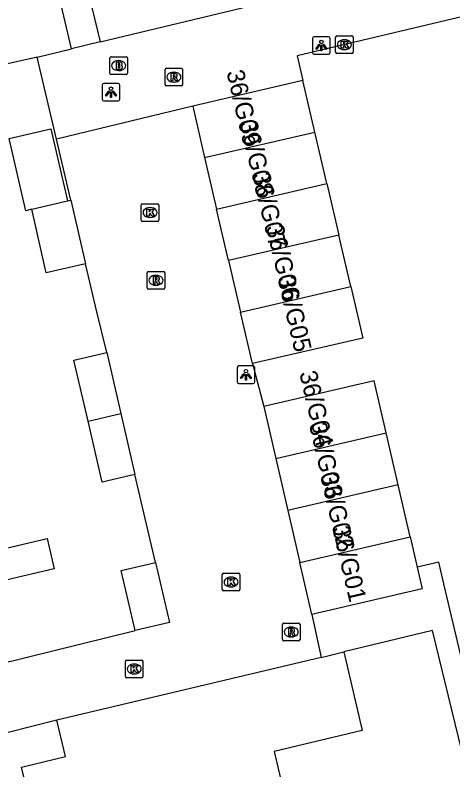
# Model space of a CAD drawing. Extents: x 158038 to 159242, y 380133 to 381214.
# Drawn here: x 158792.72 to 158817.61, y 380691.2 to 380734.09 of the extents above; entities that cross this region are included whole.
import ezdxf

# ---------------------------------------------------------------- set-up
doc = ezdxf.new("R2010")
doc.units = 0
for name, color, linetype in [('IMGEO_Brandkraan', 7, 'Continuous'), ('IMGEO_Kolk', 7, 'Continuous'), ('IMGEO_Lichtpunt', 7, 'Continuous'), ('IMGEO_Muur', 7, 'Continuous'), ('IMGEO_Pand', 7, 'Continuous'), ('IMGEO_Pand_nummerreeks', 7, 'Continuous'), ('IMGEO_Rijbaan_lokaal_open', 7, 'Continuous'), ('IMGEO_Rioolput', 7, 'Continuous'), ('IMGEO_Voetpad_open', 7, 'Continuous')]:
    doc.layers.add(name, color=color, linetype=linetype)

msp = doc.modelspace()

# ---------------------------------------------------------------- linework, layer by layer
at = {"layer": 'IMGEO_Brandkraan'}
for p, q in [((158798.109, 380730.793), (158798.109, 380731.645)), ((158798.184, 380731.719), (158799.036, 380731.719)), ((158799.11, 380731.645), (158799.11, 380730.793)), ((158798.597, 380731.499), (158798.622, 380731.499)), ((158799.036, 380730.719), (158798.184, 380730.719)), ((158798.62, 380730.939), (158798.595, 380730.939))]:
    msp.add_line(p, q, dxfattribs=at)
for points in [[(158798.109, 380730.793), (158798.109, 380731.645)], [(158798.184, 380731.719), (158799.036, 380731.719)], [(158799.11, 380731.645), (158799.11, 380730.793)], [(158798.457, 380731.419), (158798.457, 380731.019), (158798.67, 380731.019)], [(158798.688, 380731.419), (158798.457, 380731.419)], [(158798.636, 380731.338), (158798.582, 380731.338), (158798.582, 380731.262)], [(158798.582, 380731.262), (158798.635, 380731.262)], [(158798.644, 380731.186), (158798.582, 380731.186), (158798.582, 380731.105)], [(158799.036, 380730.719), (158798.184, 380730.719)], [(158798.582, 380731.105), (158798.644, 380731.105)]]:
    msp.add_lwpolyline(points, dxfattribs=at)
for centre, radius, start, end in [((158798.186, 380731.643), 0.0765, 91.552, 178.448), ((158798.186, 380731.643), 0.0765, 91.552, 178.448), ((158799.034, 380731.643), 0.0765, 1.552, 88.448), ((158799.034, 380731.643), 0.0765, 1.552, 88.448), ((158798.637, 380731.3), 0.0379, 267.8285, 90.9355), ((158798.645, 380731.145), 0.0404, 269.8759, 90.5077), ((158798.692, 380731.274), 0.145, 59.4692, 91.5367), ((158798.717, 380731.321), 0.0922, 285.5137, 58.1501), ((158798.722, 380731.129), 0.105, 301.3115, 78.989), ((158798.186, 380730.795), 0.0765, 181.552, 268.448), ((158798.186, 380730.795), 0.0765, 181.552, 268.448), ((158798.676, 380731.27), 0.251, 268.6676, 293.5347), ((158799.034, 380730.795), 0.0765, 271.552, 358.448), ((158799.034, 380730.795), 0.0765, 271.552, 358.448)]:
    msp.add_arc(centre, radius, start, end, dxfattribs=at)
for centre, major_axis, ratio, start_param, end_param in [((158798.596, 380731.219), (-0.387, 0.002), 0.722429, 4.712389, 7.853982), ((158798.621, 380731.219), (-0.39, 0.002), 0.717154, 1.570796, 4.712389)]:
    msp.add_ellipse(centre, major_axis=major_axis, ratio=ratio, start_param=start_param, end_param=end_param, dxfattribs=at)
at = {"layer": 'IMGEO_Kolk'}
for p, q in [((158810.941, 380731.983), (158810.941, 380732.835)), ((158811.016, 380732.909), (158811.868, 380732.909)), ((158811.942, 380732.835), (158811.942, 380731.983)), ((158811.429, 380732.689), (158811.454, 380732.689)), ((158811.452, 380732.129), (158811.427, 380732.129)), ((158811.868, 380731.909), (158811.016, 380731.909)), ((158799.891, 380722.443), (158799.891, 380723.295)), ((158799.966, 380723.369), (158800.818, 380723.369)), ((158800.379, 380723.149), (158800.404, 380723.149)), ((158800.892, 380723.295), (158800.892, 380722.443)), ((158800.402, 380722.589), (158800.377, 380722.589)), ((158800.818, 380722.369), (158799.966, 380722.369)), ((158804.499, 380701.449), (158804.499, 380702.301)), ((158804.574, 380702.375), (158805.426, 380702.375)), ((158804.987, 380702.155), (158805.012, 380702.155)), ((158805.5, 380702.301), (158805.5, 380701.449)), ((158805.01, 380701.595), (158804.985, 380701.595)), ((158805.426, 380701.375), (158804.574, 380701.375)), ((158798.989, 380696.509), (158798.989, 380697.361)), ((158799.064, 380697.435), (158799.916, 380697.435)), ((158799.99, 380697.361), (158799.99, 380696.509)), ((158799.477, 380697.215), (158799.502, 380697.215)), ((158799.916, 380696.435), (158799.064, 380696.435)), ((158799.5, 380696.655), (158799.475, 380696.655))]:
    msp.add_line(p, q, dxfattribs=at)
for points in [[(158810.941, 380731.983), (158810.941, 380732.835)], [(158811.016, 380732.909), (158811.868, 380732.909)], [(158811.942, 380732.835), (158811.942, 380731.983)], [(158811.262, 380732.609), (158811.385, 380732.609), (158811.385, 380732.458), (158811.515, 380732.609), (158811.679, 380732.609), (158811.533, 380732.458), (158811.686, 380732.209), (158811.534, 380732.209), (158811.449, 380732.373), (158811.385, 380732.306), (158811.385, 380732.209), (158811.262, 380732.209), (158811.262, 380732.609)], [(158811.868, 380731.909), (158811.016, 380731.909)], [(158799.891, 380722.443), (158799.891, 380723.295)], [(158799.966, 380723.369), (158800.818, 380723.369)], [(158800.212, 380723.069), (158800.335, 380723.069), (158800.335, 380722.918), (158800.465, 380723.069), (158800.629, 380723.069), (158800.483, 380722.918), (158800.636, 380722.669), (158800.484, 380722.669), (158800.399, 380722.833), (158800.335, 380722.766), (158800.335, 380722.669), (158800.212, 380722.669), (158800.212, 380723.069)], [(158800.892, 380723.295), (158800.892, 380722.443)], [(158800.818, 380722.369), (158799.966, 380722.369)], [(158804.499, 380701.449), (158804.499, 380702.301)], [(158804.574, 380702.375), (158805.426, 380702.375)], [(158804.82, 380702.075), (158804.943, 380702.075), (158804.943, 380701.924), (158805.073, 380702.075), (158805.237, 380702.075), (158805.091, 380701.924), (158805.244, 380701.675), (158805.092, 380701.675), (158805.007, 380701.839), (158804.943, 380701.772), (158804.943, 380701.675), (158804.82, 380701.675), (158804.82, 380702.075)], [(158805.5, 380702.301), (158805.5, 380701.449)], [(158805.426, 380701.375), (158804.574, 380701.375)], [(158798.989, 380696.509), (158798.989, 380697.361)], [(158799.064, 380697.435), (158799.916, 380697.435)], [(158799.99, 380697.361), (158799.99, 380696.509)], [(158799.31, 380697.135), (158799.433, 380697.135), (158799.433, 380696.984), (158799.563, 380697.135), (158799.727, 380697.135), (158799.581, 380696.984), (158799.734, 380696.735), (158799.582, 380696.735), (158799.497, 380696.899), (158799.433, 380696.832), (158799.433, 380696.735), (158799.31, 380696.735), (158799.31, 380697.135)], [(158799.916, 380696.435), (158799.064, 380696.435)]]:
    msp.add_lwpolyline(points, dxfattribs=at)
for centre, start, end in [((158811.018, 380732.833), 91.552, 178.448), ((158811.018, 380732.833), 91.552, 178.448), ((158811.866, 380732.833), 1.552, 88.448), ((158811.866, 380732.833), 1.552, 88.448), ((158811.018, 380731.985), 181.552, 268.448), ((158811.018, 380731.985), 181.552, 268.448), ((158811.866, 380731.985), 271.552, 358.448), ((158811.866, 380731.985), 271.552, 358.448), ((158799.968, 380723.293), 91.552, 178.448), ((158799.968, 380723.293), 91.552, 178.448), ((158800.816, 380723.293), 1.552, 88.448), ((158800.816, 380723.293), 1.552, 88.448), ((158799.968, 380722.445), 181.552, 268.448), ((158799.968, 380722.445), 181.552, 268.448), ((158800.816, 380722.445), 271.552, 358.448), ((158800.816, 380722.445), 271.552, 358.448), ((158804.576, 380702.299), 91.552, 178.448), ((158804.576, 380702.299), 91.552, 178.448), ((158805.424, 380702.299), 1.552, 88.448), ((158805.424, 380702.299), 1.552, 88.448), ((158804.576, 380701.451), 181.552, 268.448), ((158804.576, 380701.451), 181.552, 268.448), ((158805.424, 380701.451), 271.552, 358.448), ((158805.424, 380701.451), 271.552, 358.448), ((158799.066, 380697.359), 91.552, 178.448), ((158799.066, 380697.359), 91.552, 178.448), ((158799.914, 380697.359), 1.552, 88.448), ((158799.914, 380697.359), 1.552, 88.448), ((158799.066, 380696.511), 181.552, 268.448), ((158799.066, 380696.511), 181.552, 268.448), ((158799.914, 380696.511), 271.552, 358.448), ((158799.914, 380696.511), 271.552, 358.448)]:
    msp.add_arc(centre, 0.0765, start, end, dxfattribs=at)
for centre, major_axis, ratio, start_param, end_param in [((158811.428, 380732.409), (-0.387, 0.002), 0.722429, 4.712389, 7.853982), ((158811.453, 380732.409), (-0.39, 0.002), 0.717154, 1.570796, 4.712389), ((158800.378, 380722.869), (-0.387, 0.002), 0.722429, 4.712389, 7.853982), ((158800.403, 380722.869), (-0.39, 0.002), 0.717154, 1.570796, 4.712389), ((158804.986, 380701.875), (-0.387, 0.002), 0.722429, 4.712389, 7.853982), ((158805.011, 380701.875), (-0.39, 0.002), 0.717154, 1.570796, 4.712389), ((158799.476, 380696.935), (-0.387, 0.002), 0.722429, 4.712389, 7.853982), ((158799.501, 380696.935), (-0.39, 0.002), 0.717154, 1.570796, 4.712389)]:
    msp.add_ellipse(centre, major_axis=major_axis, ratio=ratio, start_param=start_param, end_param=end_param, dxfattribs=at)
at = {"layer": 'IMGEO_Lichtpunt'}
for p, q in [((158810.528, 380732.859), (158809.72, 380732.859)), ((158810.528, 380732.859), (158809.72, 380732.859)), ((158809.626, 380732.764), (158809.626, 380731.957)), ((158809.626, 380732.764), (158809.626, 380731.957)), ((158810.622, 380731.957), (158810.622, 380732.764)), ((158810.622, 380731.957), (158810.622, 380732.764)), ((158809.72, 380731.863), (158810.528, 380731.863)), ((158809.72, 380731.863), (158810.528, 380731.863)), ((158797.673, 380730.113), (158797.673, 380729.306)), ((158797.673, 380730.113), (158797.673, 380729.306)), ((158798.575, 380730.208), (158797.767, 380730.208)), ((158798.575, 380730.208), (158797.767, 380730.208)), ((158798.669, 380729.306), (158798.669, 380730.113)), ((158798.669, 380729.306), (158798.669, 380730.113)), ((158797.767, 380729.212), (158798.575, 380729.212)), ((158797.767, 380729.212), (158798.575, 380729.212)), ((158805.345, 380714.057), (158805.345, 380713.25)), ((158805.345, 380714.057), (158805.345, 380713.25)), ((158806.247, 380714.152), (158805.439, 380714.152)), ((158806.247, 380714.152), (158805.439, 380714.152)), ((158806.341, 380713.25), (158806.341, 380714.057)), ((158806.341, 380713.25), (158806.341, 380714.057)), ((158805.439, 380713.156), (158806.247, 380713.156)), ((158805.439, 380713.156), (158806.247, 380713.156))]:
    msp.add_line(p, q, dxfattribs=at)
for points in [[(158810, 380732.428), (158810.039, 380732.4), (158809.851, 380732.138), (158809.813, 380732.165), (158810, 380732.428)], [(158810.212, 380732.4), (158810.25, 380732.427), (158810.437, 380732.165), (158810.398, 380732.137), (158810.212, 380732.4)], [(158810.102, 380732.38), (158810.149, 380732.38), (158810.149, 380732.058), (158810.102, 380732.058), (158810.102, 380732.38)], [(158798.047, 380729.777), (158798.086, 380729.749), (158797.898, 380729.487), (158797.86, 380729.514), (158798.047, 380729.777)], [(158798.149, 380729.729), (158798.196, 380729.729), (158798.196, 380729.407), (158798.149, 380729.407), (158798.149, 380729.729)], [(158798.259, 380729.749), (158798.297, 380729.776), (158798.484, 380729.514), (158798.445, 380729.486), (158798.259, 380729.749)], [(158805.719, 380713.721), (158805.758, 380713.693), (158805.57, 380713.431), (158805.532, 380713.458), (158805.719, 380713.721)], [(158805.821, 380713.673), (158805.868, 380713.673), (158805.868, 380713.351), (158805.821, 380713.351), (158805.821, 380713.673)], [(158805.931, 380713.693), (158805.969, 380713.72), (158806.156, 380713.458), (158806.117, 380713.43), (158805.931, 380713.693)]]:
    msp.add_lwpolyline(points, dxfattribs=at)
for centre in [(158810.125, 380732.562), (158798.172, 380729.911), (158805.844, 380713.855)]:
    msp.add_circle(centre, 0.0994, dxfattribs=at)
for centre, start, end in [((158809.72, 380732.764), 90, 180), ((158809.72, 380732.764), 90, 180), ((158810.528, 380732.764), 0, 90), ((158810.528, 380732.764), 0, 90), ((158809.72, 380731.957), 180, 270), ((158809.72, 380731.957), 180, 270), ((158810.528, 380731.957), 270, 0), ((158810.528, 380731.957), 270, 360), ((158797.767, 380730.113), 90, 180), ((158797.767, 380730.113), 90, 180), ((158798.575, 380730.113), 0, 90), ((158798.575, 380730.113), 0, 90), ((158797.767, 380729.306), 180, 270), ((158797.767, 380729.306), 180, 270), ((158798.575, 380729.306), 270, 0), ((158798.575, 380729.306), 270, 360), ((158805.439, 380714.057), 90, 180), ((158805.439, 380714.057), 90, 180), ((158806.247, 380714.057), 0, 90), ((158806.247, 380714.057), 0, 90), ((158805.439, 380713.25), 180, 270), ((158805.439, 380713.25), 180, 270), ((158806.247, 380713.25), 270, 0), ((158806.247, 380713.25), 270, 360)]:
    msp.add_arc(centre, 0.0946, start, end, dxfattribs=at)
at = {"layer": 'IMGEO_Muur'}
msp.add_lwpolyline([(158791.706, 380697.195), (158799.539, 380699.123)], dxfattribs=at)
at = {"layer": 'IMGEO_Pand'}
for points in [[(158795.926, 380732.174), (158795.135, 380735.58)], [(158793.975, 380731.706), (158792.114, 380731.274), (158791.319, 380734.701)], [(158793.975, 380731.706), (158795.926, 380732.174)], [(158809.083, 380730.368), (158802.814, 380728.914)], [(158809.762, 380727.442), (158809.083, 380730.368)], [(158802.814, 380728.914), (158803.493, 380725.988)], [(158793.674, 380723.052), (158793.335, 380722.973), (158792.383, 380727.078), (158794.754, 380727.629), (158795.707, 380723.527)], [(158803.493, 380725.988), (158809.762, 380727.442)], [(158810.441, 380724.516), (158809.762, 380727.442)], [(158803.493, 380725.988), (158804.172, 380723.061)], [(158804.172, 380723.061), (158810.441, 380724.516)], [(158810.441, 380724.516), (158811.119, 380721.589)], [(158793.674, 380723.052), (158795.707, 380723.527)], [(158795.707, 380723.527), (158795.883, 380723.568)], [(158795.883, 380723.568), (158796.722, 380719.956)], [(158796.722, 380719.956), (158794.495, 380719.439), (158793.674, 380723.052)], [(158804.85, 380720.135), (158804.172, 380723.061)], [(158811.119, 380721.589), (158804.85, 380720.135)], [(158811.798, 380718.663), (158811.119, 380721.589)], [(158804.85, 380720.135), (158805.529, 380717.209)], [(158805.529, 380717.209), (158811.798, 380718.663)], [(158811.798, 380718.663), (158812.477, 380715.737), (158806.208, 380714.283)], [(158806.208, 380714.283), (158805.529, 380717.209)], [(158796.867, 380711.012), (158796.063, 380714.477), (158797.925, 380714.909)], [(158797.925, 380714.909), (158798.728, 380711.445)], [(158813.808, 380710.352), (158813.123, 380713.305), (158806.856, 380711.852)], [(158806.856, 380711.852), (158807.541, 380708.898)], [(158796.867, 380711.012), (158798.728, 380711.445)], [(158798.728, 380711.445), (158799.532, 380707.981)], [(158799.532, 380707.981), (158797.671, 380707.549), (158796.867, 380711.012)], [(158807.541, 380708.898), (158813.808, 380710.352)], [(158814.493, 380707.399), (158813.808, 380710.352)], [(158807.541, 380708.898), (158808.226, 380705.945)], [(158814.493, 380707.399), (158808.226, 380705.945)], [(158815.178, 380704.446), (158814.493, 380707.399)], [(158808.226, 380705.945), (158808.911, 380702.992)], [(158791.79, 380703.714), (158794.534, 380704.351), (158794.937, 380702.616), (158792.192, 380701.979), (158790.677, 380701.627), (158791.706, 380697.195)], [(158808.911, 380702.992), (158815.178, 380704.446)], [(158815.178, 380704.446), (158815.58, 380702.714)], [(158799.539, 380699.123), (158798.749, 380702.53), (158800.708, 380702.985)], [(158800.708, 380702.985), (158801.498, 380699.577), (158799.539, 380699.123)], [(158809.596, 380700.039), (158808.911, 380702.992)], [(158815.58, 380702.714), (158815.863, 380701.493), (158809.596, 380700.039)], [(158811.397, 380697.9), (158812.454, 380693.444), (158807.441, 380692.253), (158808.303, 380688.62)], [(158810.112, 380697.595), (158811.397, 380697.9)], [(158810.112, 380697.595), (158795.09, 380694.029)], [(158799.559, 380686.545), (158798.785, 380689.807), (158793.744, 380688.611), (158793.091, 380691.365), (158795.582, 380691.956), (158795.09, 380694.029)]]:
    msp.add_lwpolyline(points, dxfattribs=at)
at = {"layer": 'IMGEO_Rijbaan_lokaal_open'}
for points in [[(158802.814, 380728.914), (158795.077, 380727.039)], [(158795.883, 380723.568), (158795.077, 380727.039)], [(158797.925, 380714.909), (158797.37, 380717.235), (158796.722, 380719.956)], [(158806.208, 380714.283), (158806.856, 380711.852)], [(158800.708, 380702.985), (158799.532, 380707.981)], [(158809.596, 380700.039), (158810.112, 380697.595)], [(158791.706, 380697.195), (158799.539, 380699.123)], [(158795.09, 380694.029), (158784.237, 380691.279)]]:
    msp.add_lwpolyline(points, dxfattribs=at)
at = {"layer": 'IMGEO_Rioolput'}
for p, q in [((158801.244, 380730.138), (158801.244, 380730.99)), ((158801.319, 380731.064), (158802.171, 380731.064)), ((158801.732, 380730.844), (158801.757, 380730.844)), ((158802.245, 380730.99), (158802.245, 380730.138)), ((158801.755, 380730.284), (158801.73, 380730.284)), ((158802.171, 380730.064), (158801.319, 380730.064)), ((158800.227, 380718.595), (158800.227, 380719.447)), ((158800.302, 380719.521), (158801.154, 380719.521)), ((158800.715, 380719.301), (158800.74, 380719.301)), ((158801.228, 380719.447), (158801.228, 380718.595)), ((158800.738, 380718.741), (158800.713, 380718.741)), ((158801.154, 380718.521), (158800.302, 380718.521)), ((158807.915, 380698.61), (158807.915, 380699.462)), ((158807.99, 380699.536), (158808.842, 380699.536)), ((158808.916, 380699.462), (158808.916, 380698.61)), ((158808.403, 380699.316), (158808.428, 380699.316)), ((158808.842, 380698.536), (158807.99, 380698.536)), ((158808.426, 380698.756), (158808.401, 380698.756))]:
    msp.add_line(p, q, dxfattribs=at)
for points in [[(158801.244, 380730.138), (158801.244, 380730.99)], [(158801.319, 380731.064), (158802.171, 380731.064)], [(158801.833, 380730.762), (158801.581, 380730.764), (158801.581, 380730.364)], [(158802.245, 380730.99), (158802.245, 380730.138)], [(158801.581, 380730.364), (158801.705, 380730.364), (158801.705, 380730.526), (158801.716, 380730.526)], [(158801.759, 380730.683), (158801.705, 380730.683), (158801.705, 380730.602)], [(158801.705, 380730.602), (158801.757, 380730.602)], [(158801.763, 380730.497), (158801.834, 380730.364), (158801.974, 380730.364), (158801.909, 380730.49)], [(158802.171, 380730.064), (158801.319, 380730.064)], [(158800.227, 380718.595), (158800.227, 380719.447)], [(158800.302, 380719.521), (158801.154, 380719.521)], [(158800.816, 380719.219), (158800.564, 380719.221), (158800.564, 380718.821)], [(158800.742, 380719.14), (158800.688, 380719.14), (158800.688, 380719.059)], [(158801.228, 380719.447), (158801.228, 380718.595)], [(158800.564, 380718.821), (158800.688, 380718.821), (158800.688, 380718.983), (158800.699, 380718.983)], [(158800.688, 380719.059), (158800.74, 380719.059)], [(158800.746, 380718.954), (158800.817, 380718.821), (158800.957, 380718.821), (158800.892, 380718.947)], [(158801.154, 380718.521), (158800.302, 380718.521)], [(158807.915, 380698.61), (158807.915, 380699.462)], [(158807.99, 380699.536), (158808.842, 380699.536)], [(158808.916, 380699.462), (158808.916, 380698.61)], [(158808.504, 380699.234), (158808.252, 380699.236), (158808.252, 380698.836)], [(158808.252, 380698.836), (158808.376, 380698.836), (158808.376, 380698.998), (158808.387, 380698.998)], [(158808.43, 380699.155), (158808.376, 380699.155), (158808.376, 380699.074)], [(158808.376, 380699.074), (158808.428, 380699.074)], [(158808.434, 380698.969), (158808.505, 380698.836), (158808.645, 380698.836), (158808.58, 380698.962)], [(158808.842, 380698.536), (158807.99, 380698.536)]]:
    msp.add_lwpolyline(points, dxfattribs=at)
for centre, radius, start, end in [((158801.321, 380730.988), 0.0765, 91.552, 178.448), ((158801.321, 380730.988), 0.0765, 91.552, 178.448), ((158801.832, 380730.652), 0.109, 350.3612, 89.416), ((158802.169, 380730.988), 0.0765, 1.552, 88.448), ((158802.169, 380730.988), 0.0765, 1.552, 88.448), ((158801.715, 380730.473), 0.0533, 26.0293, 88.6989), ((158801.741, 380730.791), 0.19, 274.7715, 282.9687), ((158801.765, 380730.587), 0.0964, 77.0061, 93.1865), ((158801.779, 380730.644), 0.0378, 276.6634, 79.6772), ((158801.83, 380730.652), 0.112, 277.5842, 350.9817), ((158801.814, 380730.437), 0.108, 29.5134, 73.7905), ((158801.321, 380730.14), 0.0765, 181.552, 268.448), ((158801.321, 380730.14), 0.0765, 181.552, 268.448), ((158802.169, 380730.14), 0.0765, 271.552, 358.448), ((158802.169, 380730.14), 0.0765, 271.552, 358.448), ((158800.304, 380719.445), 0.0765, 91.552, 178.448), ((158800.304, 380719.445), 0.0765, 91.552, 178.448), ((158800.748, 380719.044), 0.0964, 77.0061, 93.1865), ((158800.762, 380719.101), 0.0378, 276.6634, 79.6772), ((158800.815, 380719.109), 0.109, 350.3612, 89.416), ((158801.152, 380719.445), 0.0765, 1.552, 88.448), ((158801.152, 380719.445), 0.0765, 1.552, 88.448), ((158800.698, 380718.93), 0.0533, 26.0293, 88.6989), ((158800.724, 380719.248), 0.19, 274.7715, 282.9687), ((158800.813, 380719.109), 0.112, 277.5842, 350.9817), ((158800.797, 380718.894), 0.108, 29.5134, 73.7905), ((158800.304, 380718.597), 0.0765, 181.552, 268.448), ((158800.304, 380718.597), 0.0765, 181.552, 268.448), ((158801.152, 380718.597), 0.0765, 271.552, 358.448), ((158801.152, 380718.597), 0.0765, 271.552, 358.448), ((158807.992, 380699.46), 0.0765, 91.552, 178.448), ((158807.992, 380699.46), 0.0765, 91.552, 178.448), ((158808.84, 380699.46), 0.0765, 1.552, 88.448), ((158808.84, 380699.46), 0.0765, 1.552, 88.448), ((158808.386, 380698.945), 0.0533, 26.0293, 88.6989), ((158808.412, 380699.263), 0.19, 274.7715, 282.9687), ((158808.436, 380699.059), 0.0964, 77.0061, 93.1865), ((158808.45, 380699.116), 0.0378, 276.6634, 79.6772), ((158808.503, 380699.124), 0.109, 350.3612, 89.416), ((158808.501, 380699.124), 0.112, 277.5842, 350.9817), ((158808.485, 380698.909), 0.108, 29.5134, 73.7905), ((158807.992, 380698.612), 0.0765, 181.552, 268.448), ((158807.992, 380698.612), 0.0765, 181.552, 268.448), ((158808.84, 380698.612), 0.0765, 271.552, 358.448), ((158808.84, 380698.612), 0.0765, 271.552, 358.448)]:
    msp.add_arc(centre, radius, start, end, dxfattribs=at)
for centre, major_axis, ratio, start_param, end_param in [((158801.731, 380730.564), (-0.387, 0.002), 0.722429, 4.712389, 7.853982), ((158801.756, 380730.564), (-0.39, 0.002), 0.717154, 1.570796, 4.712389), ((158800.714, 380719.021), (-0.387, 0.002), 0.722429, 4.712389, 7.853982), ((158800.739, 380719.021), (-0.39, 0.002), 0.717154, 1.570796, 4.712389), ((158808.402, 380699.036), (-0.387, 0.002), 0.722429, 4.712389, 7.853982), ((158808.427, 380699.036), (-0.39, 0.002), 0.717154, 1.570796, 4.712389)]:
    msp.add_ellipse(centre, major_axis=major_axis, ratio=ratio, start_param=start_param, end_param=end_param, dxfattribs=at)
at = {"layer": 'IMGEO_Voetpad_open'}
for points in [[(158797.553, 380732.564), (158841.648, 380743.139)], [(158830.815, 380737.027), (158808.756, 380731.773), (158809.083, 380730.368)], [(158796.613, 380736.485), (158797.553, 380732.564)], [(158797.553, 380732.564), (158795.926, 380732.174)], [(158795.077, 380727.039), (158794.525, 380729.377), (158793.975, 380731.706)], [(158846.68, 380678.256), (158823.914, 380672.887), (158821.312, 380683.919), (158819.173, 380692.991), (158817.1, 380701.78), (158816.812, 380703), (158815.58, 380702.714)], [(158823.207, 380671.374), (158816.439, 380699.129), (158811.397, 380697.9)]]:
    msp.add_lwpolyline(points, dxfattribs=at)

# ---------------------------------------------------------------- texts
at = {"layer": 'IMGEO_Pand_nummerreeks'}
for s, rotation, p in [('36/G09', 283.1164, (158804.729, 380730.855)), ('36/G08', 283.1164, (158805.479, 380727.979)), ('36/G07', 283.1164, (158806.202, 380725.037)), ('36/G06', 283.1164, (158806.975, 380722.068)), ('36/G05', 283.1164, (158807.631, 380719.144)), ('36/G04', 283.1164, (158808.872, 380713.757)), ('36/G03', 283.1164, (158809.421, 380710.837)), ('36/G02', 283.1164, (158810.054, 380707.946)), ('36/G01', 283.1148, (158810.744, 380704.94))]:
    msp.add_text(s, height=1, rotation=rotation, dxfattribs=at).set_placement(p)

doc.saveas('drawing.dxf')
